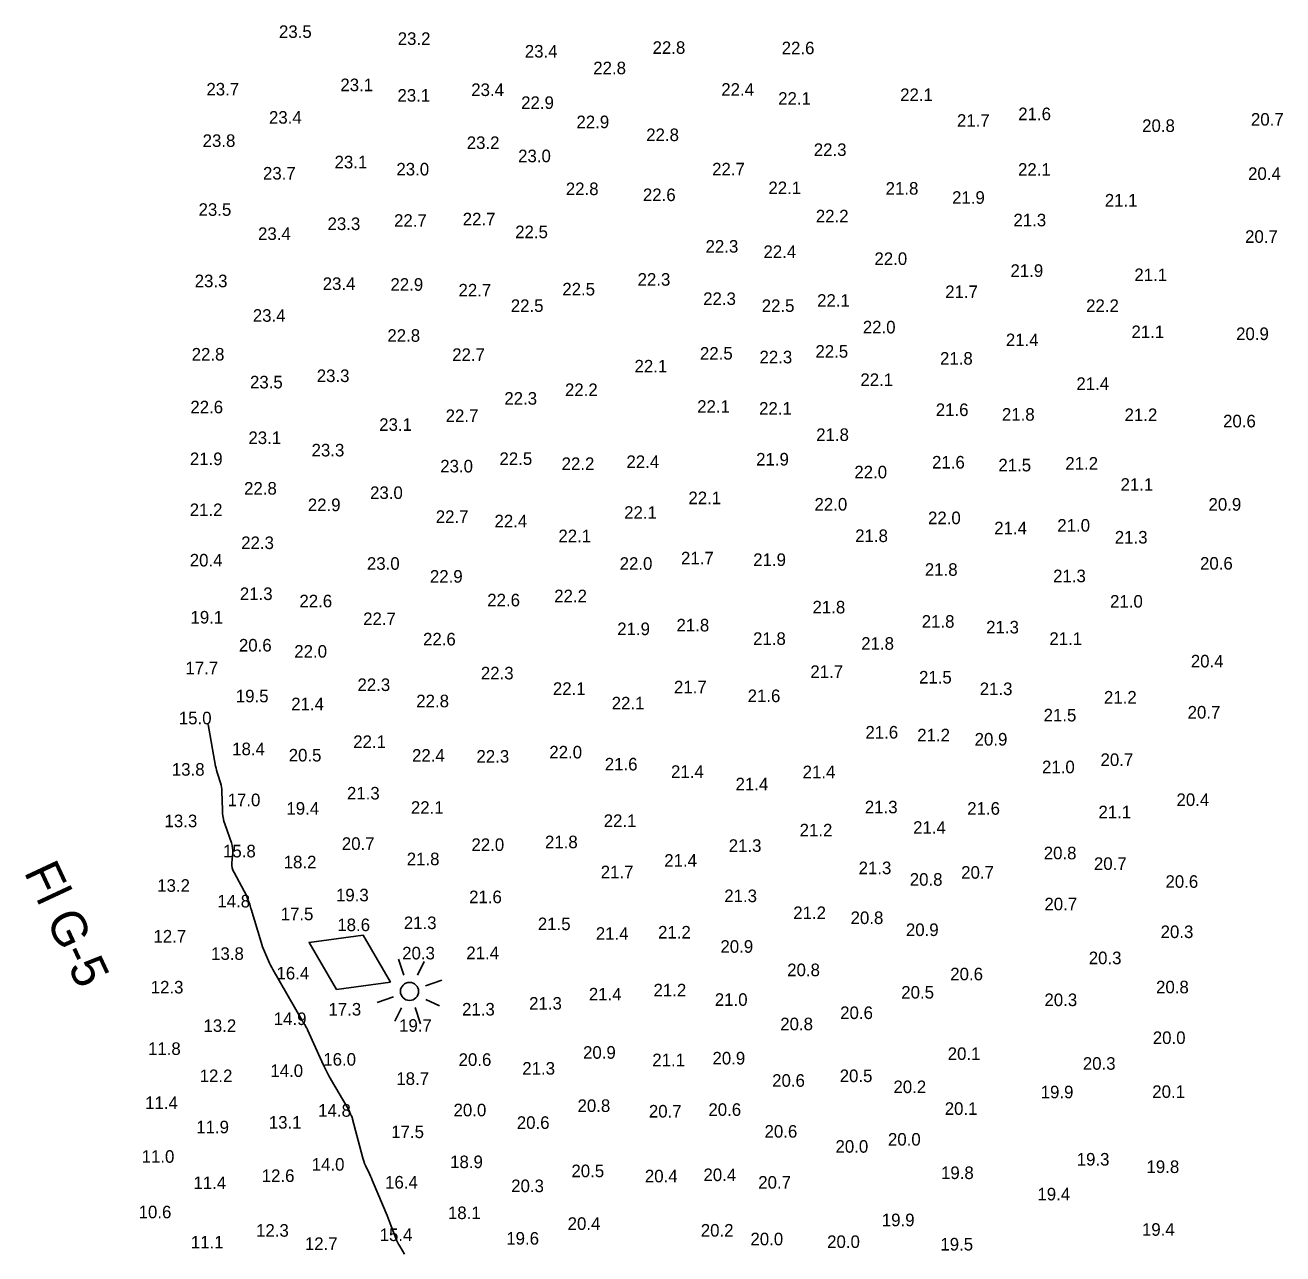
# Model space of a CAD drawing. Extents: x 1023796 to 1112670, y 656573 to 837340.
# Drawn here: x 1112142 to 1112642, y 659904 to 660392 of the extents above; entities that cross this region are included whole.
import ezdxf

# ---------------------------------------------------------------- set-up
doc = ezdxf.new("R2010")
doc.units = 0
for name, color, linetype in [('V-CHAN-CONT-15FT', 7, 'Continuous'), ('V-CHAN-NAID', 7, 'Continuous'), ('V-TOPO-SOUN', 7, 'Continuous')]:
    doc.layers.add(name, color=color, linetype=linetype)

msp = doc.modelspace()

# ---------------------------------------------------------------- linework, layer by layer
at = {"layer": 'V-CHAN-CONT-15FT'}
msp.add_lwpolyline([(1112214.57, 660114.57), (1112217.55, 660098.01), (1112217.72, 660097.15), (1112217.91, 660096.3), (1112218.14, 660095.45), (1112218.39, 660094.62), (1112219.46, 660091.28), (1112219.69, 660090.44), (1112219.87, 660089.59), (1112219.98, 660088.74), (1112220.03, 660087.87), (1112220.23, 660080.55), (1112220.32, 660079.05), (1112220.54, 660077.57), (1112220.86, 660076.11), (1112221.3, 660074.67), (1112223.84, 660067.43), (1112224.12, 660066.48), (1112224.3, 660065.5), (1112224.38, 660064.52), (1112224.35, 660063.52), (1112224.05, 660059.49), (1112224.04, 660058.5), (1112224.17, 660057.54), (1112224.44, 660056.6), (1112224.85, 660055.7), (1112229.75, 660046.5), (1112229.94, 660046.13), (1112230.11, 660045.77), (1112230.26, 660045.39), (1112230.41, 660045.01), (1112231.12, 660043.03), (1112231.17, 660042.87), (1112231.22, 660042.71), (1112231.27, 660042.55), (1112231.31, 660042.39), (1112231.47, 660041.75), (1112231.51, 660041.58), (1112231.55, 660041.42), (1112231.59, 660041.26), (1112231.64, 660041.1), (1112235.6, 660027.96), (1112235.9, 660027.01), (1112236.22, 660026.08), (1112236.58, 660025.15), (1112236.96, 660024.24), (1112238.55, 660020.6), (1112238.96, 660019.7), (1112239.4, 660018.81), (1112239.85, 660017.93), (1112240.34, 660017.07), (1112252.01, 659996.8), (1112252.1, 659996.64), (1112252.2, 659996.48), (1112252.3, 659996.32), (1112252.4, 659996.16), (1112252.8, 659995.53), (1112252.9, 659995.37), (1112253, 659995.21), (1112253.1, 659995.05), (1112253.19, 659994.89), (1112253.68, 659994), (1112253.79, 659993.79), (1112253.9, 659993.59), (1112254, 659993.38), (1112254.1, 659993.17), (1112259.74, 659980.55), (1112260.63, 659978.62), (1112261.58, 659976.72), (1112262.59, 659974.84), (1112263.64, 659973), (1112269.76, 659962.65), (1112269.95, 659962.32), (1112270.12, 659961.99), (1112270.29, 659961.66), (1112270.45, 659961.32), (1112271.22, 659959.59), (1112271.29, 659959.43), (1112271.36, 659959.27), (1112271.43, 659959.11), (1112271.5, 659958.95), (1112271.78, 659958.31), (1112271.85, 659958.15), (1112271.91, 659957.99), (1112271.96, 659957.82), (1112272.01, 659957.65), (1112275.92, 659942.66), (1112276.17, 659941.78), (1112276.46, 659940.91), (1112276.79, 659940.05), (1112277.16, 659939.22), (1112278.71, 659935.89), (1112279.09, 659935.05), (1112279.46, 659934.21), (1112279.83, 659933.37), (1112280.19, 659932.53), (1112285.68, 659919.31), (1112286.11, 659918.25), (1112286.54, 659917.2), (1112286.96, 659916.14), (1112287.37, 659915.07), (1112289.16, 659910.38), (1112289.5, 659909.54), (1112289.88, 659908.72), (1112290.3, 659907.92), (1112290.75, 659907.14), (1112292.64, 659904.05)], dxfattribs=at)
at = {"layer": 'V-CHAN-NAID'}
for p, q in [((1112292.41, 660014.84), (1112290.2, 660021.26)), ((1112297.78, 660014.89), (1112300.41, 660020.28)), ((1112307.46, 660012.84), (1112301.04, 660010.63)), ((1112288.2, 660006.21), (1112281.78, 660004)), ((1112291.46, 660001.95), (1112288.83, 659996.56)), ((1112299.04, 659995.58), (1112296.83, 660002)), ((1112301.09, 660005.26), (1112306.48, 660002.63))]:
    msp.add_line(p, q, dxfattribs=at)
msp.add_lwpolyline([(1112287.07, 660012.1), (1112276.15, 660030.78), (1112254.71, 660027.88), (1112265.63, 660009.21)], close=True, dxfattribs=at)
msp.add_circle((1112294.62, 660008.42), 3.6, dxfattribs=at)

# ---------------------------------------------------------------- texts
msp.add_text('Fl G-5', height=14, rotation=295, dxfattribs=at).set_placement((1112141.17, 660055.93))
at = {"layer": 'V-TOPO-SOUN'}
for s, p in [('23.5 ', (1112242.73, 660387.37)), ('23.2 ', (1112289.93, 660384.6)), ('22.8 ', (1112391.25, 660381.04)), ('22.6 ', (1112442.58, 660380.88)), ('23.4 ', (1112340.46, 660379.57)), ('22.8 ', (1112367.67, 660372.93)), ('23.1 ', (1112267.13, 660366.21)), ('23.7 ', (1112213.88, 660364.5)), ('23.1 ', (1112289.84, 660362.06)), ('23.4 ', (1112319.17, 660364.28)), ('22.4 ', (1112418.57, 660364.39)), ('22.1 ', (1112441.19, 660360.81)), ('22.1 ', (1112489.68, 660362.28)), ('22.9 ', (1112339.01, 660359.15)), ('23.4 ', (1112238.75, 660353.29)), ('22.9 ', (1112360.99, 660351.49)), ('21.7 ', (1112512.26, 660352.06)), ('21.6 ', (1112536.62, 660354.68)), ('20.7 ', (1112629.14, 660352.51)), ('22.8 ', (1112388.73, 660346.37)), ('20.8 ', (1112585.88, 660350.01)), ('23.8 ', (1112212.38, 660344.05)), ('23.2 ', (1112317.37, 660343.23)), ('23.1 ', (1112264.83, 660335.53)), ('23.0 ', (1112337.8, 660337.97)), ('22.3 ', (1112455.34, 660340.46)), ('23.7 ', (1112236.37, 660331.09)), ('23.0 ', (1112289.41, 660332.71)), ('22.7 ', (1112414.93, 660332.73)), ('22.1 ', (1112536.53, 660332.6)), ('20.4 ', (1112628, 660330.94)), ('22.8 ', (1112356.77, 660324.9)), ('22.6 ', (1112387.41, 660322.52)), ('22.1 ', (1112437.29, 660325.28)), ('21.8 ', (1112483.91, 660325.08)), ('21.9 ', (1112510.32, 660321.44)), ('23.5 ', (1112210.76, 660316.67)), ('21.1 ', (1112571.04, 660320.36)), ('23.3 ', (1112262.04, 660311.01)), ('22.7 ', (1112288.47, 660312.31)), ('22.7 ', (1112315.77, 660312.87)), ('22.2 ', (1112456.16, 660314.06)), ('21.3 ', (1112534.72, 660312.49)), ('23.4 ', (1112234.4, 660307.08)), ('22.5 ', (1112336.63, 660307.78)), ('20.7 ', (1112626.81, 660305.93)), ('22.3 ', (1112412.32, 660302.04)), ('22.4 ', (1112435.35, 660299.91)), ('22.0 ', (1112479.46, 660297.15)), ('21.9 ', (1112533.54, 660292.4)), ('21.1 ', (1112582.78, 660290.72)), ('23.3 ', (1112209.23, 660288.29)), ('23.4 ', (1112260.11, 660287.21)), ('22.9 ', (1112287.04, 660286.89)), ('22.3 ', (1112385.3, 660288.9)), ('22.7 ', (1112314.1, 660284.62)), ('22.5 ', (1112355.37, 660285.03)), ('22.3 ', (1112411.37, 660281.23)), ('22.1 ', (1112456.67, 660280.53)), ('21.7 ', (1112507.59, 660283.98)), ('22.5 ', (1112334.88, 660278.47)), ('22.5 ', (1112434.64, 660278.45)), ('22.2 ', (1112563.62, 660278.47)), ('23.4 ', (1112232.33, 660274.56)), ('22.8 ', (1112285.82, 660266.61)), ('22.0 ', (1112474.83, 660269.94)), ('21.1 ', (1112581.65, 660268.07)), ('20.9 ', (1112623.24, 660267.29)), ('21.4 ', (1112531.71, 660264.87)), ('22.8 ', (1112208.02, 660259.15)), ('22.7 ', (1112311.6, 660259)), ('22.5 ', (1112410.09, 660259.51)), ('22.3 ', (1112433.76, 660258.03)), ('22.5 ', (1112456, 660260.29)), ('21.8 ', (1112505.53, 660257.51)), ('23.3 ', (1112257.74, 660250.6)), ('22.1 ', (1112384.08, 660254.41)), ('23.5 ', (1112231.21, 660248.08)), ('22.1 ', (1112473.87, 660249.05)), ('21.4 ', (1112559.74, 660247.48)), ('22.3 ', (1112332.32, 660241.61)), ('22.2 ', (1112356.42, 660245.03)), ('22.6 ', (1112207.49, 660238.17)), ('22.1 ', (1112408.99, 660238.39)), ('22.1 ', (1112433.59, 660237.65)), ('21.6 ', (1112503.84, 660237.1)), ('23.1 ', (1112282.57, 660231.21)), ('22.7 ', (1112308.99, 660234.71)), ('21.8 ', (1112530.14, 660235.25)), ('21.2 ', (1112578.9, 660235.09)), ('20.6 ', (1112618.06, 660232.59)), ('23.1 ', (1112230.58, 660225.96)), ('21.8 ', (1112456.3, 660227.2)), ('23.3 ', (1112255.69, 660221.04)), ('21.9 ', (1112207.31, 660217.59)), ('22.5 ', (1112330.39, 660217.66)), ('22.2 ', (1112355.1, 660215.66)), ('22.4 ', (1112380.87, 660216.44)), ('21.9 ', (1112432.43, 660217.43)), ('21.6 ', (1112502.36, 660216.24)), ('21.2 ', (1112555.34, 660215.8)), ('23.0 ', (1112306.84, 660214.68)), ('22.0 ', (1112471.46, 660212.33)), ('21.5 ', (1112528.72, 660215.1)), ('22.8 ', (1112228.85, 660205.87)), ('21.1 ', (1112577.3, 660207.39)), ('23.0 ', (1112278.94, 660204.13)), ('22.1 ', (1112405.49, 660202.07)), ('21.2 ', (1112207.24, 660197.33)), ('22.9 ', (1112254.2, 660199.3)), ('22.1 ', (1112379.96, 660196.25)), ('22.0 ', (1112455.63, 660199.53)), ('20.9 ', (1112612.27, 660199.48)), ('22.7 ', (1112305.06, 660194.62)), ('22.4 ', (1112328.42, 660192.86)), ('22.0 ', (1112500.75, 660194.12)), ('21.0 ', (1112552.15, 660191.15)), ('22.1 ', (1112353.81, 660186.95)), ('21.8 ', (1112471.8, 660187.02)), ('21.4 ', (1112527.08, 660190.11)), ('21.3 ', (1112575.01, 660186.42)), ('22.3 ', (1112227.71, 660184.22)), ('20.4 ', (1112207.25, 660177.31)), ('23.0 ', (1112277.69, 660176)), ('22.0 ', (1112378.16, 660175.98)), ('21.7 ', (1112402.55, 660178.13)), ('21.9 ', (1112431.27, 660177.5)), ('20.6 ', (1112608.89, 660176.06)), ('22.9 ', (1112302.74, 660170.87)), ('21.8 ', (1112499.5, 660173.6)), ('21.3 ', (1112550.48, 660171.05)), ('21.3 ', (1112227.18, 660163.97)), ('22.6 ', (1112250.85, 660161.07)), ('22.6 ', (1112325.53, 660161.46)), ('22.2 ', (1112352.15, 660163.09)), ('21.0 ', (1112573.13, 660160.95)), ('21.8 ', (1112454.84, 660158.65)), ('19.1 ', (1112207.55, 660154.63)), ('22.7 ', (1112276.19, 660154.01)), ('21.8 ', (1112400.76, 660151.5)), ('21.8 ', (1112498.26, 660152.96)), ('21.3 ', (1112523.88, 660150.69)), ('22.6 ', (1112299.99, 660145.93)), ('21.9 ', (1112377.2, 660150.02)), ('21.8 ', (1112431.2, 660146.14)), ('21.1 ', (1112548.99, 660146.14)), ('20.6 ', (1112226.8, 660143.51)), ('22.0 ', (1112248.82, 660141.07)), ('21.8 ', (1112474.21, 660144.21)), ('20.4 ', (1112605.23, 660137.18)), ('17.7 ', (1112205.53, 660134.46)), ('22.3 ', (1112322.99, 660132.42)), ('21.7 ', (1112453.97, 660133)), ('21.5 ', (1112497.17, 660130.79)), ('22.3 ', (1112273.94, 660127.81)), ('22.1 ', (1112351.62, 660126.27)), ('21.7 ', (1112399.75, 660126.88)), ('21.3 ', (1112521.31, 660126.18)), ('19.5 ', (1112225.57, 660123.32)), ('22.8 ', (1112297.31, 660121.35)), ('22.1 ', (1112375, 660120.5)), ('21.6 ', (1112429.04, 660123.4)), ('21.2 ', (1112570.7, 660122.83)), ('21.4 ', (1112247.6, 660120.17)), ('21.5 ', (1112546.71, 660115.73)), ('20.7 ', (1112603.96, 660116.87)), ('15.0 ', (1112202.91, 660114.57)), ('21.6 ', (1112475.87, 660108.92)), ('21.2 ', (1112496.47, 660107.8)), ('20.9 ', (1112519.29, 660106.14)), ('18.4 ', (1112224.13, 660102.3)), ('22.1 ', (1112272.25, 660105.16)), ('22.0 ', (1112350.2, 660101.01)), ('20.5 ', (1112246.59, 660099.8)), ('22.4 ', (1112295.62, 660099.72)), ('22.3 ', (1112321.24, 660099.35)), ('21.6 ', (1112372.25, 660096.24)), ('20.7 ', (1112569.34, 660098.02)), ('13.8 ', (1112200.14, 660094.16)), ('21.4 ', (1112398.58, 660093.28)), ('21.4 ', (1112450.91, 660093.16)), ('21.0 ', (1112546.07, 660095.14)), ('21.4 ', (1112424.25, 660088.33)), ('17.0 ', (1112222.31, 660082.04)), ('21.3 ', (1112269.74, 660084.7)), ('20.4 ', (1112599.54, 660082.11)), ('19.4 ', (1112245.69, 660078.67)), ('22.1 ', (1112295.17, 660079.01)), ('21.3 ', (1112475.64, 660079.2)), ('21.6 ', (1112516.34, 660078.64)), ('21.1 ', (1112568.51, 660077.23)), ('13.3 ', (1112197.23, 660073.69)), ('22.1 ', (1112371.82, 660073.77)), ('21.4 ', (1112494.83, 660071.07)), ('21.2 ', (1112449.71, 660070.02)), ('15.8 ', (1112220.49, 660061.69)), ('20.7 ', (1112267.72, 660064.67)), ('22.0 ', (1112319.25, 660064.25)), ('21.8 ', (1112348.48, 660065.33)), ('21.3 ', (1112421.52, 660063.88)), ('20.8 ', (1112546.76, 660060.92)), ('18.2 ', (1112244.6, 660057.34)), ('21.8 ', (1112293.52, 660058.58)), ('21.4 ', (1112395.9, 660057.98)), ('20.7 ', (1112566.72, 660056.71)), ('21.7 ', (1112370.64, 660053.4)), ('21.3 ', (1112473.16, 660055.02)), ('20.7 ', (1112513.94, 660053.22)), ('13.2 ', (1112194.32, 660048.01)), ('20.8 ', (1112493.5, 660050.43)), ('20.6 ', (1112595.16, 660049.59)), ('14.8 ', (1112218.22, 660041.8)), ('19.3 ', (1112265.39, 660044.22)), ('21.6 ', (1112318.31, 660043.49)), ('21.3 ', (1112419.75, 660043.9)), ('20.7 ', (1112547.03, 660040.65)), ('17.5 ', (1112243.39, 660036.7)), ('21.2 ', (1112447.18, 660037.17)), ('18.6 ', (1112265.92, 660032.38)), ('21.3 ', (1112292.35, 660033.18)), ('21.5 ', (1112345.64, 660032.77)), ('20.8 ', (1112469.98, 660035.2)), ('12.7 ', (1112192.83, 660027.85)), ('21.4 ', (1112368.69, 660028.94)), ('21.2 ', (1112393.43, 660029.45)), ('20.9 ', (1112491.97, 660030.43)), ('20.3 ', (1112593.23, 660029.62)), ('13.8 ', (1112215.74, 660020.95)), ('20.3 ', (1112291.71, 660021.14)), ('21.4 ', (1112317.2, 660021.23)), ('20.9 ', (1112418.23, 660023.78)), ('20.3 ', (1112564.65, 660019.24)), ('16.4 ', (1112241.75, 660013.16)), ('20.8 ', (1112444.77, 660014.48)), ('20.6 ', (1112509.6, 660012.83)), ('12.3 ', (1112191.73, 660007.61)), ('21.2 ', (1112391.63, 660006.44)), ('20.5 ', (1112490.12, 660005.57)), ('20.8 ', (1112591.41, 660007.67)), ('21.3 ', (1112342.18, 660001.19)), ('21.4 ', (1112365.92, 660004.83)), ('21.0 ', (1112416, 660002.68)), ('20.3 ', (1112547.04, 660002.58)), ('17.3 ', (1112262.4, 659998.83)), ('21.3 ', (1112315.51, 659998.84)), ('20.6 ', (1112465.83, 659997.44)), ('13.2 ', (1112212.72, 659992.32)), ('14.9 ', (1112240.64, 659995.06)), ('19.7 ', (1112290.48, 659992.39)), ('20.8 ', (1112442.01, 659992.99)), ('20.0 ', (1112590.12, 659987.53)), ('11.8 ', (1112190.65, 659983.18)), ('20.9 ', (1112363.61, 659981.66)), ('20.1 ', (1112508.58, 659981.18)), ('16.0 ', (1112260.34, 659978.91)), ('20.6 ', (1112314.14, 659978.83)), ('21.1 ', (1112391.14, 659978.69)), ('20.9 ', (1112415.07, 659979.39)), ('20.3 ', (1112562.31, 659977.29)), ('12.2 ', (1112211.19, 659972.37)), ('14.0 ', (1112239.29, 659974.41)), ('18.7 ', (1112289.38, 659971.27)), ('21.3 ', (1112339.46, 659975.34)), ('20.6 ', (1112438.8, 659970.52)), ('20.5 ', (1112465.64, 659972.38)), ('20.2 ', (1112487.01, 659968)), ('19.9 ', (1112545.55, 659965.94)), ('20.1 ', (1112589.91, 659966.09)), ('11.4 ', (1112189.52, 659961.67)), ('20.8 ', (1112361.42, 659960.52)), ('14.8 ', (1112258.31, 659958.62)), ('20.0 ', (1112312.13, 659958.78)), ('20.7 ', (1112389.78, 659958.3)), ('20.6 ', (1112413.45, 659958.96)), ('20.1 ', (1112507.4, 659959.36)), ('11.9 ', (1112209.84, 659952.03)), ('13.1 ', (1112238.69, 659953.89)), ('20.6 ', (1112337.28, 659953.79)), ('17.5 ', (1112287.36, 659950.13)), ('20.6 ', (1112435.77, 659950.31)), ('20.0 ', (1112484.83, 659947.14)), ('20.0 ', (1112463.98, 659944.32)), ('11.0 ', (1112188.12, 659940.32)), ('14.0 ', (1112255.75, 659937.18)), ('18.9 ', (1112310.77, 659938.19)), ('19.3 ', (1112559.87, 659939.21)), ('19.8 ', (1112587.62, 659936.25)), ('12.6 ', (1112235.87, 659932.68)), ('20.5 ', (1112358.99, 659934.59)), ('20.4 ', (1112388.2, 659932.54)), ('20.4 ', (1112411.48, 659933.03)), ('19.8 ', (1112505.92, 659933.84)), ('11.4 ', (1112208.73, 659929.86)), ('16.4 ', (1112284.92, 659930.08)), ('20.3 ', (1112335.04, 659928.64)), ('20.7 ', (1112433.27, 659930.04)), ('19.4 ', (1112544.25, 659925.37)), ('10.6 ', (1112186.93, 659918.25)), ('18.1 ', (1112309.9, 659917.93)), ('12.3 ', (1112233.62, 659910.93)), ('20.4 ', (1112357.49, 659913.65)), ('20.2 ', (1112410.42, 659910.98)), ('19.9 ', (1112482.39, 659915.1)), ('19.4 ', (1112585.81, 659911.31)), ('11.1 ', (1112207.7, 659906.25)), ('12.7 ', (1112253.03, 659905.66)), ('15.4 ', (1112282.75, 659909.21)), ('19.6 ', (1112333.09, 659907.78)), ('20.0 ', (1112430.16, 659907.53)), ('20.0 ', (1112460.65, 659906.46)), ('19.5 ', (1112505.67, 659905.45))]:
    msp.add_text(s, height=5, dxfattribs=at).set_placement(p)

doc.saveas('drawing.dxf')
